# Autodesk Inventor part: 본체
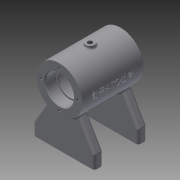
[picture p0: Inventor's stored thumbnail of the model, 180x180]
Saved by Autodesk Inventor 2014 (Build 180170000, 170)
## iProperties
Created: 2018-05
Part Number: 본체
Material: 일반
Document SubType Name: Modeling
Designer: net
Density: 1 g/cm^3
Appearance: 기본값
Author: net
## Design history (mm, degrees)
sketch "스케치1"
  geometry: L1 (-35, 0)-(35, 0); L2 (-35, 16)-(-35, 26); L3 (-35, 26)-(35, 26); L4 (35, 26)-(35, 16); L5 (35, 16)-(23, 16); L6 (23, 16)-(23, 14); L7 (23, 14)-(21, 14); L8 (21, 14)-(21, 21); L9 (21, 21)-(-21, 21); L10 (-21, 21)-(-21, 14); L11 (-21, 14)-(-23, 14); L12 (-23, 14)-(-23, 16); L13 (-23, 16)-(-35, 16); 3 further points
  constraints: 26 end point, 7 parallel, 4 perpendicular, 3 vertical alignment, 2 midpoint, 1 coincident, 1 collinear, 1 horizontal
  dimensions: "d0" = 70 distance of L1.start L1.end; "d1" = 52 diameter of L3 L1; "d2" = 32 diameter of L13 L1; "d3" = 28 diameter of L11 L1; "d4" = 42 diameter of L9 L1; "d5" = 12 distance of L12.end L2.start; "d6" = 42 distance of L8.end L9.end; "d7" = 12 distance of L4.end L5.end; "d8" = 32 diameter of L5 L1; "d9" = 28 diameter of L7 L1
revolve "회전1" sketch "스케치1" stored, may be unused: angle "d10" = 90 deg
node "작업 평면1"
sketch "스케치2"
  geometry: C1 r 5 at (0, 0); 1 further point
  constraints: 1 centre point, 1 coincident
  dimensions: "d12" = 10 diameter of C1
extrude "돌출1" join sketch "스케치2" stored distance "d13" = 10; taper "d14" = 0 deg
hole "구멍1" diameter "d17" = 5.188; stored, may be unused: countersink angle "d21" = 90 deg, drill point angle "d23" = 118 deg; dims "d18" = 29, "d19" = 4, "d20" = 2, "d22" = 30, "d61" = 10, "d62" = 10
sketch "스케치3"
  geometry: L1 (0, -26)-(0, 0); L2 (0, 0)-(9.919, -27.251); 1 further point
  constraints: 4 end point, 1 coincident, 1 vertical, 1 vertical alignment, 1 other
  dimensions: "d25" = 29 distance of L2.start L2.end; "d26" = 20 deg angle of L1 L2
node "작업 평면2"
sketch "스케치4"
  geometry: C1 r 6 at (0, 0); 1 further point
  constraints: 1 centre point, 1 coincident
  dimensions: "d27" = 12 diameter of C1
extrude "돌출2" join sketch "스케치4" stored distance "d28" = 10; taper "d29" = 0 deg
node "작업 평면3"
sketch "스케치5"
  geometry: L1 (35, -30)-(-35, -30); L2 (-35, -30)-(-35, -20); L3 (-35, -20)-(35, -20); L4 (35, -20)-(35, -30); L5 (35, -30)-(-35, -20); L6 (-35, -30)-(35, -20); L7 (26, -35)-(-26, -35) reference; 3 further points
  constraints: 12 end point, 3 midpoint, 2 parallel, 1 horizontal, 1 perpendicular, 1 vertical alignment
  dimensions: "d31" = 10 distance of L1.end L2.end; "d32" = 5 distance between parallel lines of L1 L7; "d33" = 70 distance of L2.end L3.end
extrude "돌출3" join sketch "스케치5" distance "d34" = 15; taper "d35" = 0 deg
sketch "스케치6"
  geometry: L1 (0, 15)-(70, 15) reference; L2 (0, 15)-(17.675, 45.614); L3 (70, 15)-(52.325, 45.614); A1 r 26 centre (35, 65) between (17.675, 45.614) and (52.325, 45.614) reference; 1 further point
  constraints: 4 end point, 2 point on circle
  dimensions: "d36" = 60 deg angle of L1 L2; "d37" = 60 deg angle of L3 L1
extrude "돌출4" join sketch "스케치6" distance "d38" = 10; taper "d39" = 0 deg
sketch "스케치7"
  geometry: L1 (70, 0)-(0, 0) reference; L2 (70, -10)-(70, 0) reference; 2 further points
  dimensions: "d40" = 5 distance from line of point (55, -5) L1; "d41" = 15 distance from line of L2 point (55, -5)
hole "구멍2" sketch "스케치7" at (55, -5) diameter "d42" = 4.134; stored, may be unused: countersink angle "d46" = 90 deg, drill point angle "d48" = 118 deg; dims "d43" = 8, "d44" = 4, "d45" = 2, "d47" = 10
sketch "스케치8"
  geometry: C1 r 16 at (0, 0) reference; C2 r 26 at (0, 0) reference; 1 further point
  constraints: 1 vertical alignment
  dimensions: "d49" = 21 distance of point (0, 21) C2.centre
hole "구멍3" sketch "스케치8" at (0, 21) diameter "d50" = 3.242; stored, may be unused: countersink angle "d54" = 90 deg, drill point angle "d56" = 118 deg; dims "d51" = 8, "d52" = 4, "d53" = 2, "d55" = 10
fillet "모깎기1" dims "d60" = 2
hole "구멍4" diameter "d65" = 5.188; stored, may be unused: countersink angle "d69" = 90 deg, drill point angle "d71" = 118 deg; dims "d63" = 10, "d64" = 10, "d66" = 29, "d67" = 4, "d68" = 2, "d70" = 30
fillet "모깎기2" dims "d72" = 0.3
fillet "모깎기3" dims "d73" = 3
chamfer "모따기1" distance "d74" = 1; stored, may be unused: second distance "d75" = 2, angle "d76" = 45 deg
fillet "모깎기4" dims "d77" = 3
fillet "모깎기5" dims "d78" = 3
node "작업 평면4"
sketch "스케치9"
  geometry: 2 further points
  constraints: 1 coincident, 1 other
feature "엠보싱1" sketch "스케치9" dims "d0" = 70, "d1" = 52, "d2" = 32, "d3" = 28, "d4" = 42, "d5" = 12, "d6" = 42, "d7" = 12, "d8" = 32, "d9" = 28, "d79" = 0.5, "d80" = 0
node "솔리드1"
mirror "대칭1"
mirror "대칭2"
mirror "대칭3"
pattern_circular "원형 패턴1" dims angle "d58" = 360 deg
mirror "대칭4"
other parameters: "d11" = 29, "d30" = -65
